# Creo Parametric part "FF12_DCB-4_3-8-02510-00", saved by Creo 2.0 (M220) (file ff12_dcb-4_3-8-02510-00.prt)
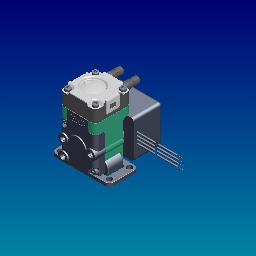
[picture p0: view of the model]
Units: millimeter Newton Second (mmNs); MM, TONNE, SECS

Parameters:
  PROI_CREATED_ON = "21.07.2008 11:36:02"
  PTC_WM_ITERATION = "13"
  PTC_WM_VERSION = "0.13"
  PTC_WM_LIFECYCLE_STATE = "in Bearbeitung"
  PTC_WM_LIFECYCLE = "KNF_EPMDocument"
  PTC_WM_LOCATION = "/Bibliotheken/Standard/Startmodels"
  PTC_WM_CREATED_BY = "Sven Fehrenbach (sfehrenbach: KNF)"
  PTC_WM_CREATED_ON = "15-Aug-08 02:26:31 PM"
  PTC_WM_MODIFIED_BY = "Produktmanager Flodos (pm1300: KNF)"
  PTC_WM_MODIFIED_ON = "30-Aug-16 08:35:49 AM"
  MATERIAL = "UNASSIGNED"
  PTC_MATERIAL_NAME = "UNASSIGNED"
  COPY_GEOM_ORIGIN_TYPE = "Part"

Other parameters: GEWICHT, VOLUMEN

Created from: KNF_STD_PART_SOLID.PRT

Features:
  1. coordinate system
  2. datum plane "RIGHT"
  3. datum plane "TOP"
  4. datum plane "FRONT"
  5. datum axis
  6. datum axis
  7. datum axis
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
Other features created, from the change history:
  planar section "A"
  planar section "B"
  planar section "C"
  patch "Verbundvolumen 1"

Other named items: A_X, A_Y, A_Z

Layers: AXIS-ACHSEN, CONSTR_ELEM-KONSTR_ELEM, GEOM_ELEMENT-GEOM_ELEMENT, MASSE, NOT_GEOM_ELEM-NICHT_GEOM_ELEM, PARAMETERDIM-PARAMETERBEM, PLANES-EBENEN, STANDARD-STANDARD, STD_AXIS-STD_ACHSEN, STD_COORD-STD_KOORDS, STD_PLANES-STD_EBENEN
